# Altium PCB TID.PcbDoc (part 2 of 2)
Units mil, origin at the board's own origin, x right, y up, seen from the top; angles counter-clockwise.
Board outline 3536 x 3093.63 mil, 4 copper layers (Top Layer, Ground plane, Supply plane, Bottom Layer), stack 79.834 mil thick; 234 components, 122 nets, 591 pads, 178 vias.
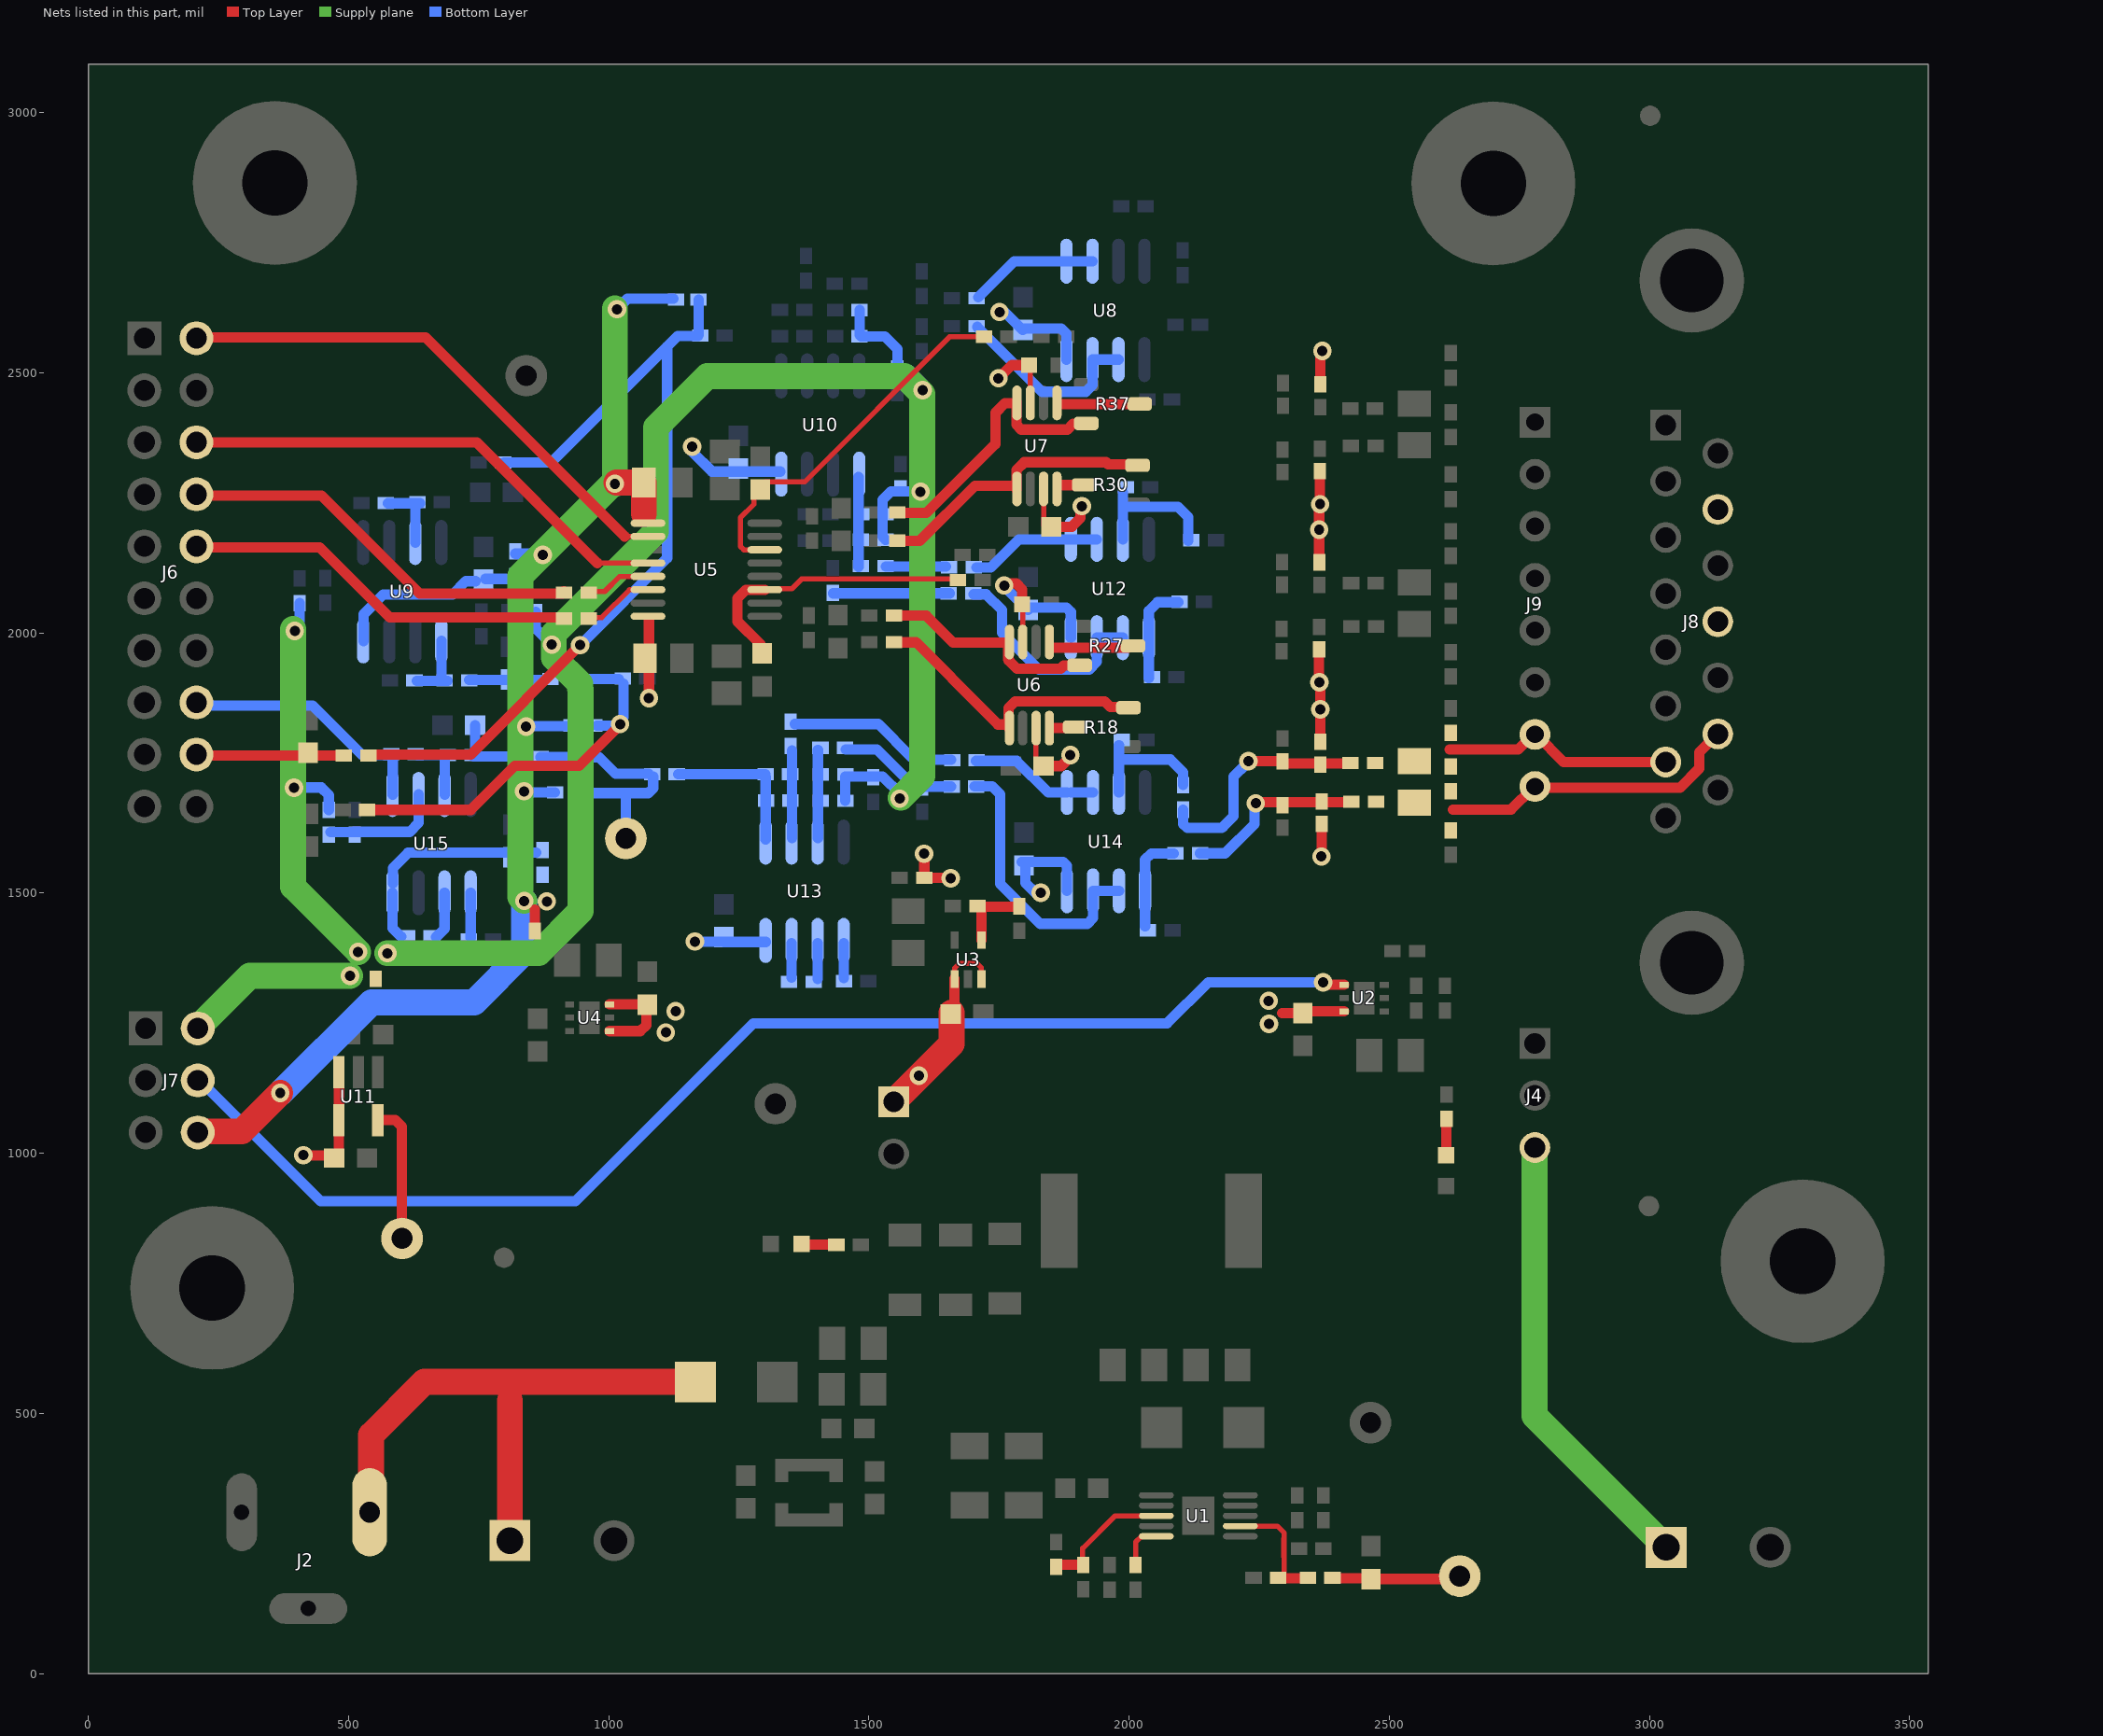
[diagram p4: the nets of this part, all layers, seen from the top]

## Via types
v1: diameter 35.43, hole 19.68, Top Layer to Bottom Layer, 169 vias
v2: diameter 19.68, hole 7.87, Top Layer to Bottom Layer, 9 vias

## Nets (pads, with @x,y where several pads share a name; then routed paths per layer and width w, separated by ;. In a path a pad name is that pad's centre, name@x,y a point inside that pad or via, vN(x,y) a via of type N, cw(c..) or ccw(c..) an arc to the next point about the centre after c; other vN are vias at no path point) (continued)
NetC65_1: C65.1 R60.2 U12.5 | length 192.8
  Bottom Layer w20: C65.1@2037.95,1913.26 U12.5@2037.95,1991.06 2037.95,2042.89 2054.17,2059.11 R60.2@2094.41,2059.11
NetC66_1: C66.1 R61.2 R62.1 | length 224.5
  Bottom Layer w20: R62.1@1430.96,2076.25 R61.2@1655.47,2076.25
NetC67_1: C67.1 R64.2 R65.1 | length 142.6
  Bottom Layer w20: R65.1@731.94,1909.76 R64.2@874.54,1909.76
NetC68_1: C68.1 R67.2 R68.1 | length 115.6
  Bottom Layer w20: R68.1@1532.78,2127.67 R67.2@1648.36,2127.67
NetC69_1: C69.1 R69.2 U12.3 | length 269.9
  Bottom Layer w20: U12.3@1987.95,2180.04 C69.1@1987.95,2270.07 ; 1987.98,2242.64 2094.03,2242.64 2113.8,2222.88 R69.2@2113.8,2177
NetC71_2: C71.2 R68.2 R70.1 U10.5 | length 172
  Bottom Layer w20: R68.2@1479.95,2127.42 U10.5@1479.95,2299.42
NetC72_1: C72.1 R74.2 R79.1 U13.1 | length 287.7
  Bottom Layer w20: R79.1@1133.08,1728.61 R74.2@1301.34,1728.61 ; U13.1@1301.52,1603.6 R74.2@1301.52,1723.05
NetC72_2: C72.2 R74.1 R78.2 U13.2 | length 168
  Bottom Layer w20: U13.2@1352,1606.16 R78.2@1352,1774.11
NetC76_1: C76.1 R75.2 U15.2 | length 232.4
  Bottom Layer w20: R75.2@465.03,1617.71 C76.1@511.27,1617.71 ; C76.1@510.32,1617.83 617.36,1617.83 634.9,1635.36 U15.2@634.9,1689.68
NetC77_1: C77.1 R76.2 U14.3 | length 247.9
  Bottom Layer w20: U14.3@1980.56,1693.57 C77.1@1980.56,1784.55 ; 1981.67,1756.87 2079.21,1756.87 2104.04,1732.04 R76.2@2104.04,1707.78
NetC78_1: C78.1 R77.2 R78.1 | length 322.5
  Bottom Layer w20: R78.1@1357.73,1825.16 1517.75,1825.16 1582.11,1760.81 C78.1@1602.64,1760.81 ; C78.1@1606.65,1756.33 R77.2@1657.57,1756.33
NetC79_1: C79.1 R80.2 R81.1 | length 137
  Bottom Layer w20: R81.1@740.18,1762.85 R80.2@821.54,1762.85 ; R81.1@743.46,1767.21 C79.1@743.46,1822.86
NetC80_1: C80.1 R85.2 R86.1 | length 231.4
  Bottom Layer w20: R86.1@1455.79,1776.37 1515.3,1776.37 1586.83,1704.84 R85.2@1657.56,1704.84
NetC81_1: C81.1 R87.2 U14.5 | length 188
  Bottom Layer w20: C81.1@2030.56,1436.07 U14.5@2030.56,1504.59 2030.56,1564.26 2042.51,1576.22 R87.2@2085.38,1576.22
NetC83_2: C83.2 R86.2 R88.1 U13.3 | length 168.8
  Bottom Layer w20: U13.3@1402,1606.16 R86.2@1402,1775
NetD1_2: D1.2 J1.1 J2.1 | length 1087.4
  Top Layer w50: J2.1@543.56,310.16 543.56,458.99 645.47,560.9 D1.2@1170.53,560.9 ; J1.1@810.05,255.8 810.05,525.22
NetD3_1: D3.1 R2.1 | length 57.4
  Top Layer w20: D3.1@1370.04,824.65 R2.1@1427.44,824.65
NetD4_1: D4.1 R12.1 | length 57.6
  Top Layer w20: D4.1@2609.49,996.1 R12.1@2609.49,1053.67
NetD17_2: D17.2 R41.1 R48.2 R49.1 | length 1659.7
  Top Layer w20: R41.1@548.56,1766.42 734.89,1766.42 v1@944.4,1975.93
  Bottom Layer w20: R49.1@798.89,2327.52 889.14,2327.52 1112.24,2550.62 ; v1@950.93,1982.47 1112.24,2143.78 1112.24,2550.62 ; R48.2@1172.05,2570.73 1132.35,2570.73 1112.24,2550.62 ; R48.2@1172.52,2572.56 D17.2@1172.52,2640.75
  other v1: 944.95,1976.82
NetD18_2: D18.2 R57.1 R63.2 R64.1 | length 758.6
  Top Layer w20: R57.1@535.95,1660.15 735.03,1660.15 819.57,1744.69 943.24,1744.69 v1@1020.53,1821.98
  Bottom Layer w20: R64.1@935.68,1911.44 R63.2@1019.61,1911.44 ; D18.2@977.25,1821.67 1012.59,1821.67 1028.75,1837.83 R63.2@1028.75,1902.67
  other v1: 1021.85,1824.97
NetD19_2: D19.2 R79.2 R80.1 TP6.1 | length 474.9
  Bottom Layer w20: R80.1@868.79,1761.49 980.97,1761.49 1012.87,1729.58 R79.2@1076.68,1729.58 ; D19.2@940.01,1693.87 941.51,1692.37 1075.99,1692.37 1085.48,1701.86 R79.2@1085.48,1724.31 ; TP6.1@1032.87,1605.27 1032.87,1686.57
NetJ4_3: J4.3 J5.1 | length 874.4
  Supply plane w50: J4.3@2779.1,1012.35 2779.1,495.67 J5.1@3032.01,242.76
NetR3_1: R3.1 R5.2 U1.3 | length 256.3
  Top Layer w10: R5.2@1910.87,213.86 1910.87,241.08 1973.22,303.43 U1.3@2063.99,303.43
  Top Layer w20: R3.1@1861.91,209.33 R5.2@1912.09,209.33
NetR6_2: R6.2 R7.2 TP2.1 | length 242.8
  Top Layer w20: R7.2@2398.32,183.43 R6.2@2467.3,183.43 ; R6.2@2464.7,181.94 TP2.1@2638.53,181.94
NetR7_1: R7.1 R10.2 U1.7 | length 216.2
  Top Layer w10: U1.7@2225.4,283.75 2284.71,283.75 2298.17,270.29 2298.17,260.07 2297.48,259.38 2297.48,225.09 2298.17,224.4 R10.2@2298.17,183.67
  Top Layer w20: R10.2@2298.17,183.67 R7.1@2348.81,183.67
NetR8_2: R8.2 U1.5 | length 99.7
  Top Layer w10: R8.2@2012.54,209.24 2012.54,252.89 2023.71,264.06 U1.5@2063.99,264.06
NetR15_1: R15.1 R16.2 U3.4 | length 141.5
  Top Layer w20: R15.1@1705.17,1474.08 R16.2@1789.27,1474.08 ; U3.4@1716.08,1409.64 R15.1@1716.08,1467.02
NetR18_2: R18.2 R21.1 U6.5 | length 553.7
  Top Layer w20: R21.1@1553.74,1982.15 1590.4,1982.15 1727.01,1845.54 1727.01,1845.08 1747.77,1824.32 U6.5@1767.18,1824.32 ; U6.5@1768.2,1818.26 1768.2,1856.16 1780.88,1868.84 1952.62,1868.84 ; 1952.79,1868.3 1963.56,1857.53 R18.2@1995.4,1857.53
NetR18_3: R18.3 U6.8 | length 42.5
  Top Layer w20: 1857.62,1817.65 R18.3@1900.14,1817.65
NetR22_1: R22.1 U5.13 | length 126.2
  Top Layer w10: R22.1@961.26,2079.79 992.05,2079.79 1021.06,2108.8 U5.13@1075.43,2108.8
NetR25_1: R25.1 R27.2 U6.4 | length 416.4
  Top Layer w20: R25.1@1550.75,2033.93 1609.99,2033.85 1661.99,1981.84 1767.95,1981.84 1767.95,1949.82 1768.84,1948.94 1768.84,1947.03 1784.5,1931.37 1865.1,1931.37 ; 1868.58,1931.81 1874.36,1937.59 R27.2@1905.9,1937.59
NetR26_1: R26.1 U5.14 | length 136.3
  Top Layer w10: R26.1@961.26,2029.79 986.63,2029.79 1040.05,2083.21 U5.14@1075.43,2083.21
NetR27_3: R27.3 U6.1 | length 142.2
  Top Layer w20: 1856.2,1972.01 R27.3@1998.43,1972.01
NetR30_2: R30.2 R33.1 U7.5 | length 531.9
  Top Layer w20: R33.1@1562.04,2177.07 1597.47,2177.07 1703.61,2283.21 U7.5@1781.09,2283.21 ; U7.5@1783.29,2276.78 1783.29,2313.04 1798.51,2328.25 1955.47,2328.25 1959.75,2323.98 2003.71,2323.98 R30.2@2006.61,2321.08
NetR30_3: R30.3 U7.8 | length 51.7
  Top Layer w20: U7.8@1865.87,2284.35 R30.3@1917.55,2284.35
NetR36_1: R36.1 R37.2 U7.4 | length 524
  Top Layer w20: R36.1@1559.13,2230.7 1610.46,2230.7 1743.04,2363.28 1743.04,2423.27 1761.31,2441.53 1773.86,2441.53 ; U7.4@1783.29,2442.91 1783.29,2400.44 1792.94,2390.78 ; 1793.9,2390.92 1881.17,2390.92 1892.43,2402.18 R37.2@1919.96,2402.18
NetR37_3: R37.3 U7.1 | length 144.9
  Top Layer w20: U7.1@1869.59,2439.58 R37.3@2014.45,2439.58
NetR46_1: R46.1 U8.1 U8.2 | length 246.5
  Bottom Layer w20: R46.1@1709.83,2645.53 1778.91,2714.6 U8.1@1879.56,2714.6 ; U8.1@1881.45,2714.6 U8.2@1929.56,2714.6
NetR50_2: R50.2 R51.1 U9.3 | length 136.9
  Bottom Layer w20: R51.1@575.95,2249.33 R50.2@637.45,2249.33 ; U9.3@628.74,2173.78 R50.2@628.74,2249.15
NetR52_1: R52.1 U8.6 U8.7 | length 376.4
  Bottom Layer w20: R52.1@1708.51,2588.21 1833.17,2463.55 1916.7,2463.55 1929.56,2476.41 U8.7@1929.56,2525.63 ; U8.7@1930.36,2525.63 U8.6@1979.56,2525.63
NetR61_1: R61.1 U12.6 U12.7 | length 424
  Bottom Layer w20: R61.1@1701.44,2074.34 1725.54,2074.34 1755.54,2044.34 1755.54,2000.74 1826.48,1929.8 1923.14,1929.8 1937.95,1944.61 U12.7@1937.95,1991.06 ; U12.7@1938.44,1991.06 U12.6@1987.95,1991.06
NetR65_2: R65.2 R66.1 U9.5 | length 132.1
  Bottom Layer w20: R66.1@631.04,1908.33 R65.2@690.25,1908.33 ; R65.2@678.74,1911.96 U9.5@678.74,1984.81
NetR67_1: R67.1 U12.1 U12.2 | length 249.1
  Bottom Layer w20: R67.1@1706.76,2125.78 1733.93,2125.78 1788.19,2180.04 U12.1@1887.95,2180.04 ; U12.1@1892.49,2180.04 U12.2@1937.95,2180.04
NetR71_1: R71.1 U13.7 | length 65.8
  Bottom Layer w20: R71.1@1351.52,1337.75 U13.7@1351.52,1403.6
NetR71_2: R71.2 U13.6 | length 68.4
  Bottom Layer w20: R71.2@1401.52,1335.17 U13.6@1401.52,1403.6
NetR72_2: R72.2 U13.5 | length 66.6
  Bottom Layer w20: R72.2@1451.52,1336.99 U13.5@1451.52,1403.6
NetR77_1: R77.1 U14.1 U14.2 | length 241.8
  Bottom Layer w20: R77.1@1705.88,1754.21 1783.91,1754.21 1844.56,1693.57 U14.1@1880.56,1693.57 ; U14.1@1888.55,1693.57 U14.2@1930.56,1693.57
NetR81_2: R81.2 R83.1 U15.3 | length 135.6
  Bottom Layer w20: R83.1@632.2,1765.69 R81.2@684.9,1765.69 ; U15.3@684.9,1689.68 R81.2@684.9,1765.69 ; R81.2@691.79,1765.69 R81.2@684.9,1765.69
NetR82_2: R82.2 U15.6 | length 92
  Bottom Layer w20: R82.2@668.32,1415.5 684.59,1431.76 U15.6@684.59,1500.74
NetR84_2: R84.2 U15.5 | length 86.3
  Bottom Layer w20: R84.2@734.59,1414.46 U15.5@734.59,1500.74
NetR85_1: R85.1 U14.6 U14.7 | length 545.2
  Bottom Layer w20: R85.1@1702.6,1705.49 1736.91,1705.44 1751.99,1690.36 1751.99,1518.33 1829.14,1441.18 1919.59,1441.18 1930.56,1452.14 U14.7@1930.56,1504.59 U14.6@1980.56,1504.59
NetTP5_1: TP5.1 U11.5 | length 259.3
  Top Layer w20: U11.5@557.26,1063.94 589.74,1063.94 602.19,1051.49 TP5.1@602.19,842.28
PWR_EN: J7.4 U2.4 | length 2453.3
  Top Layer w20: v1@2383.37,1323.96 U2.4@2413.27,1323.96
  Bottom Layer w20: J7.4@220.49,1137.18 220.49,1133.94 446.48,907.95 936,907.95 1277.51,1249.46 2072.79,1249.46 2152.03,1328.7 v1(2372.76,1328.7)
R: J6.16 R83.2 U15.1 | length 484.9
  Bottom Layer w20: J6.16@213.75,1860.75 430.95,1860.75 526.01,1765.69 R83.2@584.96,1765.69 ; U15.1@584.9,1689.68 R83.2@584.9,1763.99
R_M: C43.1 C44.2 J8.7 J9.7 R38.1 R39.2 | length 448
  Top Layer w20: 2615.99,1775.95 2747.65,1775.95 2775.3,1803.61 2783.29,1803.61 2834.77,1752.12 J8.7@3031.24,1752.12
R_M1: D13.1 D14.2 R38.2 R76.1 | length 431.9
  Top Layer w20: v1(2229.18,1753.78) D13.1@2288.35,1753.78 ; D13.1@2295.19,1749.08 R38.2@2423.5,1749.08
  Bottom Layer w20: R76.1@2104.04,1660.53 2104.04,1632.93 2111.6,1625.38 2178.2,1625.38 ; 2180.87,1627.91 2200.62,1647.66 2200.62,1723.89 v1@2225.6,1748.87
R_P: C44.1 C45.2 J8.14 J9.8 R39.1 R40.1 | length 591.3
  Top Layer w20: 2622.64,1660.27 2733.73,1660.27 2776.09,1702.62 3058.56,1702.62 3095.85,1739.91 3095.85,1770.67 J8.14@3131.24,1806.06 ; J9.8@2777.49,1704.45 J9.8@2780.5,1707.46
R_P1: D15.1 D16.2 R40.2 R87.1 | length 351.1
  Top Layer w20: v1@2249.82,1674.73 D15.1@2295.78,1674.73 ; D15.1@2293.22,1674.73 R40.2@2430.57,1674.83
  Bottom Layer w20: R87.1@2136.34,1576.66 2184.78,1576.66 2241.17,1633.06 v1@2241.17,1672.64
  other v1: 2243.25,1672.68
REFIO: C57.1 C58.1 C70.1 C71.1 C82.1 C83.1 J7.2 R44.1 R55.2 R56.2 R59.1 R70.2 R75.1 R88.2 | length 4573.5
  Supply plane w50: J7.2@211.57,1242.58 310.03,1341.04 v1(502.83,1341.04) ; v1@393.78,2007.48 393.78,1512.07 v1(518.54,1387.3) ; v1(574.41,1384.68) 865.23,1384.68 946.18,1465.64 946.18,1891.45 944.8,1892.83 944.8,1902.68 894.36,1953.13 894.36,1998.95 1090.73,2195.32 1090.73,2395.34 1189.38,2493.99 1568.49,2493.99 1602.7,2459.78 1602.7,1724.83 v1@1561.26,1683.39
  Bottom Layer w20: v1@399.32,1703.11 447.59,1703.11 462.14,1688.56 R75.1@462.14,1660.15 ; v1@406.03,2017.26 R44.1@406.03,2057.27 ; R59.1@859.58,2041 859.58,2008.75 v1(890.66,1977.67) ; C83.1@1454.62,1677.58 1454.62,1724.33 1526.34,1724.33 v1@1559.94,1690.73 ; R55.2@1482.05,2620.49 1482.05,2572.87 1484.69,2570.24 1530.43,2570.24 1554.74,2545.92 1554.74,2505.14 1578.12,2505.14 v1@1605.23,2478.04 ; R70.2@1532.09,2179.3 1526.46,2184.93 1526.46,2255.9 1542.7,2272.14 v1@1598.6,2272.14
  other v1: 1558.95,1681.74 395.37,1702.52 396.77,2004.07 1599.12,2271.63 1603.1,2466.88
REFIO_A: R24.1 R28.2 U5.3 | length 540.8
  Top Layer w10: U5.3@1301.12,2084.97 1351.69,2084.97 1370.76,2104.04 R24.1@1667.05,2104.04
  Top Layer w20: R28.2@1291.96,1977.8 1247.37,2022.39 1247.37,2067.1 1263.47,2083.21 U5.3@1299.84,2083.21
REFIO_B: R29.2 R35.1 U5.6 | length 720.7
  Top Layer w10: R29.2@1278.73,2274.22 1278.73,2247.24 1253.13,2221.64 1253.13,2166.68 1259.83,2159.98 U5.6@1299.84,2159.98 ; R29.2@1288.59,2276.57 1302.5,2290.48 1376.13,2290.48 1654.86,2569.21 R35.1@1720.43,2569.21
SCLK: J6.6 U5.12 | length 963.3
  Top Layer w10: 978.08,2134.39 U5.12@1075.43,2134.39
  Top Layer w20: J6.6@208.12,2366.1 746.38,2366.1 978.08,2134.39
SDI: J6.2 U5.10 | length 1015.7
  Top Layer w10: 1030.79,2185.57 U5.10@1075.43,2185.57
  Top Layer w20: J6.2@218.19,2568.15 648.21,2568.15 1030.79,2185.57
SDO_A: J6.8 R22.2 | length 782.7
  Top Layer w20: J6.8@210.89,2263.81 448.47,2263.81 636.5,2075.78 910.01,2075.78 R22.2@914.02,2079.79
SDO_B: J6.10 R26.2 | length 761.1
  Top Layer w20: J6.10@208.81,2164.8 444.23,2164.8 579.24,2029.79 R26.2@914.02,2029.79
SENSOR_GND: J8.10
SENSOR_UP: J8.12
SIN: C48.1 J6.18 R41.2 | length 282.2
  Top Layer w20: J6.18@208.95,1764.49 209.22,1764.77 R41.2@491,1764.77
V3_3_DC: C27.2 D17.1 D18.1 D19.1 J7.6 R17.2 R42.2 R73.2 U5.9 | length 2551.2
  Top Layer w20: R17.2@858.18,1427.34 858.22,1468.12
  Top Layer w50: J7.6@205.77,1042.06 294.92,1042.06 v1(368.79,1115.92) ; v1@1015.16,2289.06 C27.2@1067.54,2289.06 1067.54,2229.04
  Supply plane w50: v1(837.69,1485.15) 830.01,1492.83 830.01,2109.54 v1@1002.67,2282.2 ; v1(1011.86,2286.77) v1@1011.86,2624.08
  Bottom Layer w20: R42.2@820.09,2152.43 v1@871.31,2152.43 ; v1@839.27,1821 D18.1@930.02,1821 ; v1@842.89,1693.87 D19.1@896.7,1693.87 ; v1@870.58,2153.15 v1(873.47,2150.26) ; v1(1015.69,2622.27) 1036.04,2642.62 D17.1@1123.95,2642.62
  Bottom Layer w50: v1@369.48,1115.99 543.91,1290.43 741.42,1290.43 837.69,1386.7 v1(837.69,1485.15)
  other v1: 881.05,1484.11 837.59,1695.81 841.29,1819.99
V5_DC: C23.2 C24.2 C25.2 C33.2 C34.2 C47.2 C50.2 C59.2 C62.2 C73.2 C75.2 D6.1 D8.1 D10.1 D12.1 D14.1 D16.1 R14.2 U5.16 U6.3 U6.7 U7.3 U7.7 U8.8 U10.8 U11.3 U11.4 U12.8 U13.8 U14.8 | length 2372.9
  Top Layer w10: U6.3@1795.57,1982.71 C24.2@1795.57,2051.66 ; U7.3@1810.1,2442.25 C34.2@1810.1,2513.87 ; C23.2@1821.16,1753.28 U6.7@1821.16,1817.35 ; C33.2@1835.7,2207.96 U7.7@1835.7,2276.9
  Top Layer w20: v1@410.02,996.2 C59.2@474.86,996.2 ; C59.2@481.45,1004.34 U11.4@481.45,1064.41 ; U11.4@481.72,1064.06 U11.3@481.72,1158.55 ; U11.3@482.45,1158.43 U11.3@482.45,1163.54 ; v1(1077.21,1874.85) 1077.21,2024.5 ; v1@1606.53,1562.59 R14.2@1606.53,1529.56 v1@1643.89,1529.56 ; v1@1750.4,2490.87 1774.39,2514.85 C34.2@1807.74,2514.85 ; v1@1764.82,2095.26 1783.15,2095.26 1794.31,2084.11 C24.2@1794.31,2055.28 ; C23.2@1835.63,1744.36 1869.75,1744.36 v1@1885.85,1760.46 ; C33.2@1850.38,2204.18 1889.75,2204.18 1906.53,2220.97 v1@1906.53,2245.59 ; v1@2365.05,1909.18 D6.1@2365.05,1968.55 ; D8.1@2365.2,2136.99 v1(2365.2,2198.67) v1@2365.2,2244.62 ; v1@2366.48,2254.83 D12.1@2366.48,2311.29 ; D10.1@2367.3,2477.69 v1@2367.3,2538.17 ; D14.1@2367.53,1790.76 v1@2367.53,1850.29 ; v1(2367.62,1853.4) v1@2367.62,1898.15 ; v1@2369.92,1567.51 D16.1@2369.92,1633.27
  Bottom Layer w20: v1(1160.45,2358.14) 1160.45,2348.28 1198.38,2310.35 U10.8@1329.57,2310.35 ; v1@1167.96,1407.01 C75.2@1224.28,1407.01 ; C75.2@1221.84,1406.16 U13.8@1302,1406.16 ; v1@1761.43,2616.33 C47.2@1792.47,2585.29 ; v1@1766.75,2083.95 1769.51,2081.19 1769.51,2080.52 C62.2@1801.41,2048.63 ; C73.2@1793.67,1560.01 1873.48,1560.01 1880.56,1552.93 U14.8@1880.56,1504.59 ; C47.2@1796.17,2582.26 1795.5,2582.26 C47.2@1792.47,2585.29 ; C73.2@1800.94,1554.33 1800.94,1519.92 1819.93,1500.93 v1(1830.36,1500.93) ; C62.2@1806.08,2044.62 1805.41,2044.62 C62.2@1801.41,2048.63 ; U8.8@1879.56,2525.63 1879.56,2575.19 1869.46,2585.29 C47.2@1792.47,2585.29 ; U12.8@1887.95,1991.06 1887.95,2040.36 1879.69,2048.63 C62.2@1801.41,2048.63
  other v1: 413.01,996.46 1165.57,1407.01 1657.18,1528.68 2369.63,1570.44 1605.85,1575.8 1887.1,1765.47 2365.8,1905.4 1760,2091.4 1908.97,2243.76 2367.01,2247.64 1748.85,2489.46 2371.42,2542.07 1750.97,2616.83
V6_DC: C17.1 C19.1 C21.1 J3.1 U2.6 U3.1 U3.3 U4.4 U4.6 | length 647.2
  Top Layer w10: U3.1@1664.9,1334.83 1664.9,1356.13 1673.93,1365.16 1707.59,1365.16 1715.7,1357.05 U3.3@1715.7,1339.68
  Top Layer w20: U4.4@1001.72,1235.05 1060.99,1235.05 1072.16,1246.22 C21.1@1072.16,1277.13 ; U4.6@1001.72,1286.23 C21.1@1068.16,1286.23 ; C19.1@1664.08,1276.32 U3.1@1664.08,1335.56 ; 2294.46,1269.71 C17.1@2333.77,1269.71 ; 2354.56,1272.78 U2.6@2413.27,1272.78
  Top Layer w50: J3.1@1545.27,1096.56 1659.04,1210.33 C19.1@1659.04,1270.42
  other v1: 1595.75,1149.24 1109.66,1232.42 2268.76,1248.86 1128.5,1273.24 2268.17,1293.06
V_DC1: C49.2 R42.1 U9.8 | length 343.2
  Bottom Layer w20: U9.8@528.74,1984.81 528.74,2035.87 566.9,2074.03 700.12,2074.03 725.65,2099.56 C49.2@744.25,2099.56 ; C49.2@762.97,2103.95 R42.1@813.19,2103.95
V_DC2: C74.2 R73.1 R82.1 U15.8 | length 407.9
  Bottom Layer w20: U15.8@584.59,1500.74 584.59,1432.94 R82.1@601.01,1416.51 ; U15.8@585.36,1519.31 585.36,1548.7 614.63,1577.97 860.69,1577.97
pads on no net: FID1.1 FID2.1 FID3.1 H1.1 H2.1 H3.1 H4.1 J8.5 J8.6 J8.8 J8.13 J8.15 J8.16 J8.17 U1.6 U2.5 U4.5 U15.7

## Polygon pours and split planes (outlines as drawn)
A_P on Top Layer "Top Layer-A_P" (solid, remove dead copper, pour order 40): 2629.77,2503.09 2626.42,2506.44 2618.67,2506.44 2519.79,2506.44 2456.53,2443.18 2456.53,2419.7 2468.09,2408.13 2625.15,2408.13 2629.87,2412.86
A_M on Top Layer "Top Layer-A_M" (solid, remove dead copper, pour order 37): 2629.91,2389.97 2627.52,2392.36 2624.84,2392.36 2478.51,2392.36 2457.65,2371.51 2457.65,2347.67 2516.56,2288.76 2625.21,2288.76 2629.79,2293.34
B_P on Top Layer "Top Layer-B_P" (solid, remove dead copper, pour order 36): 2629.79,2046.43 2627.38,2048.84 2623.56,2048.84 2482.89,2048.84 2458.54,2024.5 2458.54,2000.64 2511.35,1947.83 2624.67,1947.83 2629.82,1952.98
B_M on Top Layer "Top Layer-B_M" (solid, remove dead copper, pour order 35): 2629.9,2161.26 2627.1,2164.06 2622.9,2164.06 2514.37,2164.06 2458.09,2107.78 2458.09,2083.89 2477.47,2064.51 2628.18,2064.49 2629.97,2066.38
R_P on Top Layer "Top Layer-R_P" (solid, remove dead copper, pour order 34): 2629.78,1612.93 2629.78,1709.24 2627.28,1711.74 2482.46,1711.74 2458.3,1687.58 2458.3,1663.9 2516.83,1605.34 2614.81,1605.34 2625.9,1605.34 2629.79,1609.23
R_M on Top Layer "Top Layer-R_M" (solid, remove dead copper, pour order 33): 2620.97,1823.57 2518.2,1823.57 2456.73,1762.09 2456.73,1738.12 2467.2,1727.65 2628.34,1727.65 2629.98,1729.28 2629.9,1820.98 2627.26,1823.62 2625.96,1823.62
REFIO on Top Layer "Top Layer-refio" (solid, remove dead copper, pour order 38): 508.58,1404.58 581.25,1404.58 593.1,1392.74 593.1,1335.95 577.38,1320.22 496.75,1320.22 483.04,1333.94 483.04,1379.04
NetC1_1 on Top Layer "Top Layer-SW" (solid, remove dead copper, pour order 49): 2204.94,336.63 2195.56,336.63 2184.03,348.15 2164.19,367.99 2164.19,402.31 2164.19,940.36 2184.83,961 2256.09,961 2259.64,957.46 2259.64,342.4 2253.75,336.51
GND on Top Layer "Top Layer-PS_GND" (solid, remove dead copper, pour order 58): 1975.42,1141.42 1287.8,1141.42 1247.49,1101.11 1244.13,1097.75 1244.13,992.48 1244.13,920.8 1054.87,731.54 1041.44,718.11 591.24,718.11 395.25,522.12 252.34,379.22 252.34,164.66 252.34,122.03 294.98,79.4 314.65,59.72 490.09,59.72 2644.57,59.72 2738.03,153.18 2738.03,320.79 2525.37,533.45 2525.37,818.38 2201.87,1141.88
GND on Top Layer "Top Layer-ENC_GND" (solid, remove dead copper, pour order 56): 2684.34,1454.54 2340.04,1454.54 2323.38,1437.88 2211.18,1325.68 2211.18,1207.48 2363.95,1054.71 2590.83,827.83 2590.83,555.81 3029.49,117.15 3277.6,117.15 3330.36,169.9 3330.36,464.22 2932.58,862 2932.58,1206.29 2775.96,1362.91
V3_3_DC on Top Layer "Top Layer-V3_3_out" (solid, remove dead copper, pour order 45): 880.08,1501.47 886.74,1501.47 898.06,1490.15 898.06,1479.33 885.41,1466.68 877.59,1466.68 876.26,1465.35 867.43,1456.52 849.62,1456.52 838.8,1467.34 835.31,1467.34 832.31,1467.34 820.82,1478.83 820.82,1491.98 830.48,1501.63
V6_DC on Top Layer "Top Layer-ldoenc-vin" (solid, remove dead copper, pour order 44): 2252.78,1247.63 2252.78,1300.4 2261.24,1308.86 2276.35,1308.86 2285.41,1299.8 2285.41,1291.74 2299.71,1277.44 2299.71,1260.32 2287.42,1248.03 2287.42,1245.21 2276.55,1234.34 2266.07,1234.34 2252.78,1247.63
NetD1_2 on Top Layer "Top Layer-vin" (solid, remove dead copper, pour order 46): 900.45,552.7 829.74,481.98 819.21,481.98 788.36,481.98 721.41,548.94
NetC5_1 on Top Layer "Top Layer-filter" (solid, remove dead copper, pour order 48): 1287.25,597.1 1287.25,499.2 1321.67,464.78 1321.67,382.93 1335.44,369.17 1442.52,369.17 1452.46,379.11 1452.46,655.23 1440.99,666.7 1352.27,666.7 1285.72,600.16
NetC2_1 on Top Layer "Top Layer-Vdcdc" (solid, remove dead copper, pour order 41): 1902.49,851.76 1902.49,793.71 1888.12,779.35 1531.83,779.35 1521.48,789.69 1521.48,1013.81 1532.98,1025.31 1849.62,1025.31 1902.49,972.44
NetC15_2 on Top Layer "Top Layer-Venc_fb" (solid, remove dead copper, pour order 43): 2537.86,1396.1 2537.86,1307.54 2539.21,1306.19 2624.03,1306.19 2626.27,1308.43 2626.27,1347.62 2573.25,1400.64 2542.4,1400.64
NetC18_1 on Top Layer "Top Layer-ldo5v" (solid, remove dead copper, pour order 42): 1570.95,1440.52 1607.41,1440.52 1655.02,1392.91 1674.49,1392.91 1676.99,1395.41 1676.99,1488.63 1675.33,1490.3 1544.32,1490.3 1543.32,1489.3 1543.32,1442.19 1544.98,1440.52
NetC15_1 on Top Layer "Top Layer-ldo5V" (solid, remove dead copper, pour order 47): 2544.22,1290.02 2775.83,1290.02 2808.91,1256.93 2808.91,1179.08 2787.18,1157.34 2523.78,1157.34 2517.62,1163.51 2517.62,1267.31 2540.32,1290.02
V6_DC on Top Layer "Top Layer-ldo_3_3V-vin" (solid, remove dead copper, pour order 39): 1055.58,1305.53 1119.83,1305.53 1145.06,1280.3 1145.06,1242.96 1116.13,1214.03 1108.06,1214.03 1055.58,1266.5
GND on Top Layer "Top Layer-GND" (solid, remove dead copper, pour order 57): 139.82,2672.04 946.87,2672.04 1162.42,2887.59 2102.31,2887.59 2383.59,2606.31 2706.86,2606.31 2850.17,2463 2850.17,1623.33 2850.17,1563.7 2791.9,1505.43 2759.38,1472.91 2434.16,1472.91 2252.58,1472.91 2161.79,1382.12 2034.49,1254.82 1296.67,1254.82 960.53,918.69 156.28,918.69 62.78,1012.19 62.78,2594.99
V3_3_DC on Bottom Layer "Bottom Layer-3_3V" (solid, remove dead copper, pour order 55): 868.04,1550.99 860,1550.99 826.12,1517.12 819.79,1510.78 819.79,1475.44 829.54,1465.69 887.3,1465.69 888.76,1465.69 898.51,1475.44 898.51,1536.86 884.37,1550.99
GND on Bottom Layer "Bottom Layer-GND" (solid, remove dead copper, pour order 62): 141.05,2672.44 947,2672.44 1163.72,2889.16 2101.36,2889.16 2384.3,2606.23 2707.03,2606.23 2850.17,2463.09 2850.17,1623.33 2850.17,1563.7 2791.9,1505.43 2759.38,1472.91 2434.16,1472.91 2252.58,1472.91 2161.79,1382.12 2033.91,1254.24 1300.07,1254.24 964.52,918.69 332.44,918.69 156.28,918.69 62.78,1012.19 62.78,2594.16
NetD19_2 on Bottom Layer "Bottom Layer-testpt" (solid, pour order 54): 1041.45,1665.89 1062.18,1686.62 1062.18,1694.78 1015.83,1694.78 1007.18,1686.13 1031,1662.3 1033.45,1662.3
V3_3_DC on Supply plane "Supply plane-V3_3" (solid, remove dead copper, pour order 32): 846.08,1459.64 883.46,1459.64 899.48,1475.67 899.48,1566.99 855.42,1611.05 855.42,2090.36 926.19,2161.12 1036.74,2271.67 1036.74,2613.2 1036.74,2636.7 1019.38,2654.06 807.85,2654.06 733.73,2579.94 733.73,1551.17 825.26,1459.65
REFIO on Supply plane "Supply plane-REFIO" (solid, remove dead copper, pour order 51): 620.33,1405.15 600.94,1424.53 502.59,1424.53 495.64,1424.53 473.67,1402.56 473.67,1379.19 456.42,1361.95 456.42,1354.44 456.42,1316.89 456.98,1316.34 531.52,1316.34
V5_DC on Supply plane "Supply plane-V5_DC" (solid, remove dead copper, pour order 61): 1176.04,1329.92 2108.84,1329.92 2251.66,1472.74 2452.37,1472.74 2507.48,1527.86 2507.48,2482.71 2327.28,2662.91 1341.5,2662.91 1135.83,2457.24 1135.83,2027.34 1044.6,1936.1 1044.6,1830.95 1097.17,1778.37 1097.17,1535.59 853.58,1291.99 470.07,1291.99 354.91,1176.82 354.91,944.87 381.48,918.29 725.79,918.29 1136.5,1329
V6_DC on Supply plane "Supply plane-V6DC" (solid, remove dead copper, pour order 53): 2266.63,1302.24 2278.87,1302.24 2295.69,1285.42 2295.69,1254.82 2287.28,1246.41 2277.48,1236.6 1788.55,1236.6 1728.08,1236.6 1561.22,1069.74 1522.02,1069.74 1382.03,1209.73 1099.82,1209.73 1091.43,1218.12 1091.43,1260.27 1132.72,1301.56 2274.58,1301.56 2275.7,1302.68
GND on Ground plane "Ground plane-PS_GND" (solid, remove dead copper, pour order 60): 1972.22,1141.42 1284.61,1141.42 1244.29,1101.11 1240.93,1097.75 1240.93,992.48 1240.93,920.8 1051.67,731.54 1038.24,718.11 588.04,718.11 392.06,522.12 249.15,379.22 249.15,164.66 249.15,122.03 291.78,79.4 311.46,59.72 486.9,59.72 2641.37,59.72 2734.83,153.18 2734.83,324.54 2525.59,533.78 2525.59,814.96 2198.67,1141.88
GND on Ground plane "Ground plane-GND" (solid, remove dead copper, pour order 59): 139.87,2672.44 946.97,2672.44 1163.7,2889.16 2098.98,2889.16 2381.54,2606.6 2706.36,2606.6 2850.17,2462.8 2850.17,1623.33 2850.17,1563.7 2791.9,1505.43 2759.38,1472.91 2434.16,1472.91 2252.58,1472.91 2161.79,1382.12 2034.49,1254.82 1299.99,1254.82 963.86,918.69 332.44,918.69 156.28,918.69 62.78,1012.19 62.78,2595.35
GND on Ground plane "Ground plane-GND connection" (solid, remove dead copper, pour order 50): 1241.01,1093.34 1199.3,1135.04 1168.57,1135.04 1168.57,1190.65 1284.9,1306.98 2036.3,1306.98 2233.12,1503.79 2314.33,1503.79 2326.5,1491.62 2301.17,1466.29 2301.17,1458.59 2305.22,1454.54 2348.02,1454.54 2362.62,1439.94 2362.62,1274.79 2258.72,1170.89 2226.53,1170.89 2216.29,1160.65 2205.31,1149.67 2205.31,1110.17 2159.22,1064.07 1271.74,1064.07 1269.54,1064.07 1241.74,1091.87
GND on Ground plane "Ground plane-ENC_GND" (solid, remove dead copper, pour order 52): 2684.47,1454.31 2340.17,1454.31 2323.51,1437.65 2210.57,1324.72 2210.57,1207.99 2364.08,1054.48 2591.9,826.66 2591.9,555.4 3030.38,116.92 3277.73,116.92 3330.49,169.68 3330.49,463.99 2933.44,861.04 2933.44,1205.34 2776.09,1362.68

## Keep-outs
Keep-Out Layer:
  lines w6: -3,0 ccw(c0,0) 0,-3 ; -3,0 ccw(c0,0) 0,-3 ; -3,0 -3,3093.63 ; -3,3093.63 cw(c0,3093.63) 0,3096.63 ; -3,3093.63 cw(c0,3093.63) 0,3096.63 ; 0,-3 3536,-3 ; 0,3096.63 3536,3096.63 ; 3536,-3 ccw(c3536,0) 3539,0 ; 3536,-3 ccw(c3536,0) 3539,0 ; 3536,3096.63 cw(c3536,3093.63) 3539,3093.63 ; 3536,3096.63 cw(c3536,3093.63) 3539,3093.63 ; 3539,0 3539,3093.63
  text ".Layer_Name" at 577,-858.49 h60

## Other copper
Top Layer:
  pour cut-out: 2163.87,520.61 2163.87,553.51 2155.65,561.74 2103.89,561.74 2103.89,429.98 2097.19,423.28 2023.36,423.28 2016.52,423.27 2015.68,422.43 2015.68,418.02 2016.59,417.11 2160.79,417.11 2165.24,421.56
  pour cut-out: 1180.84,1899.01 1184.87,1903.04 1184.87,2326.34 1179.94,2331.27 1177.25,2331.27 1173.22,2327.24 1173.22,1902.14 1176.36,1899.01
  pour cut-out: 1835.67,761.61 1835.67,746.44 1922.9,659.2 2152.37,659.2 2158.06,664.89 2158.06,944.3 2181.45,967.68 2255.41,967.68 2255.41,987.28 2161.85,1080.84 1922.9,1080.84 1859.69,1017.62 1907.73,969.58 1907.73,777.41 1901.41,771.09 1845.78,771.09 1835.67,760.98
  pour cut-out: 2037.31,195.59 2037.31,143.87 2043.55,137.64 2204.63,137.64 2214.6,147.61 2214.6,243.89 2213.04,245.45 2210.55,245.45 2210.55,150.11 2202.44,142.01 2202.44,140.76 2045.1,140.76 2041.05,144.81 2041.05,196.22 2037.94,199.33
  pour cut-out: 1919.31,689.1 1907.75,677.54 1907.75,640.2 1911.31,636.65 2150.43,636.65 2161.99,648.2 2161.99,663.32 2136.21,689.1
  pour cut-out: 2767.52,2248.34 2762.43,2248.34 2739.38,2225.3 2739.38,2185.64 2762.87,2162.15 2800.98,2162.15 2821.58,2182.76 2821.58,2225.08 2798.54,2248.12
  pour cut-out: 1592.07,1061.29 1592.07,1046.72 1571.18,1025.82 1503.07,1025.82 1503.07,1058.35 1506.01,1061.29
  text ".Layer_Name" at 577,-858.49 h60
Ground plane:
  pour cut-out: 2767.52,2248.34 2762.43,2248.34 2739.38,2225.3 2739.38,2185.64 2762.87,2162.15 2800.98,2162.15 2821.58,2182.76 2821.58,2225.08 2798.54,2248.12
  pour cut-out: 2813.84,2225.98 2853.7,2225.98 2858.58,2221.09 2858.58,2187.63 2853.61,2182.66 2814.81,2182.66 2810.06,2187.41 2810.06,2222.2
Bottom Layer:
  pour cut-out: 2767.52,2248.34 2762.43,2248.34 2739.38,2225.3 2739.38,2185.64 2762.87,2162.15 2800.98,2162.15 2821.58,2182.76 2821.58,2225.08 2798.54,2248.12
  text ".Layer_Name" at 577,-858.49 h60

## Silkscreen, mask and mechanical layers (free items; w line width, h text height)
Top Overlay:
  lines w10: 85.92,1568.73 100.92,1583.73 ; 86.77,1342.78 101.77,1327.78 ; 100.92,1540.41 100.92,1583.73 ; 101.77,1371.1 101.77,1327.78 ; 115.92,1568.73 100.92,1583.73 ; 116.77,1342.78 101.77,1327.78
  text ".CopyrightYear" at 3220.15,2911.04 h60
  text "©" at 3140.37,2906.35 h105
  text ".PRJ_Number" at 1442.33,2806.88 h60
  text ".PCB_Rev" at 2114.75,2806.88 h60
  text "SDI" at 279.42,2551.37 h30
  text "CSN" at 279.42,2452.76 h30
  text "SCLK" at 279.42,2348.62 h30
  text "SDO_A" at 279.42,2257.39 h30
  text "SDO_B" at 279.42,2156.93 h30
  text "A" at 279.42,2062.1 h30
  text "B" at 279.42,1955.95 h30
  text "R" at 279.42,1844.38 h30
  text "SIN" at 279.42,1758.06 h30
  text "COS" at 279.42,1641.6 h30
  text "GND" at 87.65,1500.92 h30 r270
  text "REFIO" at 275.52,1222.86 h30
  text "PWR_EN" at 275.52,1121.58 h30
  text "3.3V" at 275.52,1023.22 h30
  text "24V" at 731.73,50.41 h40
  text "GND" at 988.82,48.46 h40
  text "Ext Venc" at 2862.51,41.19 h40
  text "GND" at 3216.93,37.75 h40
  text ".Layer_Name" at 577,-858.49 h60
Bottom Overlay:
  lines w8: 843.42,1949.37 1009.9,1950.08 1031.54,1972.97 1031.67,1972.97 ; 1271.99,2739.63 1282.7,2739.61 ; 1282.54,2596.2 1295.84,2596.2 ; 1282.55,2737.98 1282.66,2596.65 ; 1620.88,2212.28 1641.18,2233.76 ; 1629.89,2503.61 1687.23,2443.7
  lines w10: 1573.03,1610.06 1582.47,1621.52
  text ".Layer_Name" at 577,-858.49 h60
Top Paste:
  text ".Layer_Name" at 577,-858.49 h60
Bottom Paste:
  text ".Layer_Name" at 577,-858.49 h60
Top Solder:
  text ".Layer_Name" at 577,-858.49 h60
  text ".Layer_Name" at 577,-858.49 h60
Bottom Solder:
  text ".Layer_Name" at 577,-858.49 h60
Drill Guide:
  text ".Layer_Name" at 577,-858.49 h60
M1 Board Outline:
  the board outline again, w10
  text ".Layer_Name" at 577,-858.49 h60
M2 Board Dimensions:
  rectangle: 125,-400 500,-275
  rectangle: 0,-275 125,-150
  lines w7: 0,-275 1000,-275 ; 125,-400 125,-150 ; 250,-400 250,-150 ; 500,-400 500,-150 ; 750,-400 750,-150 ; 0,-400 0,-150 1000,-150 1000,-400 0,-400
  text ".Layer_Name" at 577,-858.49 h60
M3 3D STEP Top:
  text ".Layer_Name" at 577,-858.49 h60
M4 3D STEP Bottom:
  text ".Layer_Name" at 577,-858.49 h60
M5 Assembly Top:
  lines w10: -292,-930.17 6308,-930.17 ; -292,-726.83 6310,-726.83 ; -292,-523.5 -292,-1133.5 3713,-1133.5 6310,-1133.5 6310,-523.5 -291.5,-523.5 -291.5,-1133.5 1284,-1133.5 ; 2173,-1133.5 2173,-523.5 ; 3440,-726.83 3440,-523.5 ; 4280,-726.83 4280,-523.5 ; 4902,-1140 4902,-937.17
  text "COMPONENTS MARKED 'DNP' SHOULD NOT BE POPULATED." at 1153.5,-318.5 h60
  text "ASSEMBLY VARIANT:" at 1153,-434 h60
  text ".VariantName" at 2189,-434 h60
  text "PCB VIEWED FROM TOP SIDE" at -228.5,-655.67 h60
  text "BOARD #:" at 2248,-655.67 h60
  text ".PRJ_Number" at 2793.5,-655.67 h60
  text "REV:" at 3638,-655.67 h60
  text ".PCB_Rev" at 3929.5,-655.67 h60
  text "SVN REV:" at 4476,-655.67 h60
  text ".VersionControl_RevNumber" at 4982,-655.67 h60
  text "PLOT NAME =" at -228.5,-1064.34 h60
  text ".plot_File_Name" at 577,-1064.34 h60
  text "GENERATED    :" at 2250,-1064.34 h60
  text ".Print_Date" at 3119.5,-1064.34 h60
  text ".Print_Time" at 3848.5,-1064.34 h60
  text "TEXAS INSTRUMENTS" at 5113,-1064.34 h60
M6 Assembly Bottom:
  lines w10: -292.5,-727.33 6309.5,-727.33 ; -290.5,-930.67 6309.5,-930.67 ; 1115.5,-1140.5 1115.5,-937.67 ; 1737.5,-727.33 1737.5,-524 ; 2577.5,-727.33 2577.5,-524 ; 3844.5,-1134 3844.5,-524 ; 4733.5,-1134 6309,-1134 6309,-524 -292.5,-524 -292.5,-1134 2304.5,-1134 6309.5,-1134 6309.5,-524
  text "COMPONENTS MARKED 'DNP' SHOULD NOT BE POPULATED." at 6102,-318 h60
  text ".VariantName" at 5058,-434 h60
  text "ASSEMBLY VARIANT:" at 6097,-434 h60
  text ".VersionControl_RevNumber" at 1035.5,-656.17 h60
  text "SVN REV:" at 1541.5,-656.17 h60
  text ".PCB_Rev" at 2088,-656.17 h60
  text "REV:" at 2379.5,-656.17 h60
  text ".PRJ_Number" at 3224,-656.17 h60
  text "BOARD #:" at 3769.5,-656.17 h60
  text "PCB VIEWED FROM BOTTOM SIDE" at 6246,-656.17 h60
  text "TEXAS INSTRUMENTS" at 904.5,-1064.84 h60
  text ".Print_Time" at 2169,-1064.84 h60
  text ".Print_Date" at 2898,-1064.84 h60
  text "GENERATED    :" at 3767.5,-1064.84 h60
  text ".plot_File_Name" at 5440.5,-1064.84 h60
  text "PLOT NAME =" at 6246,-1064.84 h60
M9 Title Sheet:
  drawing of 57 lines, arcs and shapes, not listed
  text "1" at 739.84,8036.5 h70
  text "2" at 3235.5,8036.5 h70
  text "3" at 5724.84,8036.5 h70
  text "4" at 8231.51,8036.5 h70
  text "5" at 10730.5,8036.5 h70
  text "6" at 13235.5,8036.5 h70
  text "A" at -416.5,6893.5 h70
  text "A" at 14383.5,6893.5 h70
  text "B" at -416.5,4513.5 h70
  text "B" at 14383.5,4513.5 h70
  text "C" at -416.5,2138.5 h70
  text "C" at 14383.5,2138.5 h70
  text "PROJECT TITLE:" at 11343.5,277.5 h45
  text ".PRJ_Title" at 11393.5,144.17 h70
  text "DESIGNED FOR:" at 11343.5,-23.5 h45
  text ".PRJ_Customer" at 11393.5,-163.5 h70
  text "D" at -416.5,-231.5 h70
  text "D" at 14383.5,-231.5 h70
  text "FILE NAME:" at 11343.5,-323.5 h45
  text ".PCB_File_Name_No_Path" at 11393.5,-443.5 h70
  text "Texas Instruments (TI) and/or its licensors do not warrant the accuracy or completeness of this specification" at 6374,-605.34 h45
  text "ENGINEER:" at 11343.5,-613.5 h45
  text "LAYOUT BY:" at 12848.5,-613.5 h45
  text "or any information contained therein. TI and/or its licensors do not warrant that this design will meet" at 6329.01,-718 h45
  text ".PRJ_Engineer" at 11393.5,-768.49 h70
  text ".PCB_Layout" at 12899,-768.49 h70
  text "the specifications, will be suitable for your application or fit for any particular purpose, or will operate in" at 6329.01,-830.67 h45
  text ".Layer_Name" at 577,-858.49 h60
  text "ALTIUM DESIGNER VERSION:" at 12848.5,-923.5 h45
  text "an implementation. TI and/or its licensors do not warrant that the design is production worthy. You should" at 6329.01,-943.33 h45
  text "completely validate and test your design implementation to confirm the system functionality for your application." at 6374,-1056 h45
  text ".print_Scale" at 11393.5,-1056.83 h70
  text ".Application_BuildNumber" at 12899,-1056.83 h70
  text "1" at 739.84,-1263.5 h70
  text "2" at 3235.5,-1263.5 h70
  text "3" at 5724.84,-1263.5 h70
  text "4" at 8231.51,-1263.5 h70
  text "5" at 10730.5,-1263.5 h70
  text "6" at 13235.5,-1263.5 h70
M10 Fab Notes:
  drawing of 185 lines, arcs and shapes, not listed
  text "DESIGN INFORMATION" at 12381.02,5910 h60
  text "MIN. TRACK WIDTH:" at 11736.46,5730 h60
  text "8" at 12832.7,5730 h60
  text "MIL" at 12987.46,5730 h60
  text "MIN. CLEARANCE:" at 11736.46,5598 h60
  text "0.2" at 12772.7,5598 h60
  text "mm" at 12987.46,5598 h60
  text "MIN. VIA PAD SIZE:" at 11736.46,5466 h60
  text "24" at 12802.71,5466 h60
  text "MIL" at 12987.46,5466 h60
  text "0.05mm (2MIL)" at 12431.46,5324.29 h60
  text "MINIMUM ANNULAR RING" at 11407.23,5320 h60
  text "EXTERNAL" at 13139.46,5320 h60
  text "PER" at 11607.23,5202 h60
  text "IPC-D-275 CLASS 2 LEVEL C" at 11827.23,5202 h60
  text "MIL, HOLES" at 13315.46,5089.71 h60
  text "+/-" at 12923,5089 h60
  text "+/-" at 13777,5089 h60
  text "REGISTRATION TOLERANCES:" at 11407.23,5084 h60
  text "METAL" at 12607,5084 h60
  text "5" at 13183.2,5084 h60
  text "3" at 14016.2,5084 h60
  text "MIL" at 14132.46,5084 h60
  text "MATERIAL:" at 11332.46,4874.54 h60
  text "FR-4 High Tg" at 12318.9,4734.21 h60
  text "FR-408" at 11753.46,4725.64 h60
  text "X" at 12165.46,4725.64 h60
  text "OTHER" at 13241.46,4725.64 h60
  text "62 MIL (1.6mm) +/-10%" at 12073.56,4562.92 h60
  text "THICKNESS:" at 11407.23,4558.64 h60
  text "X" at 11945.4,4558.64 h60
  text "OTHER" at 13358.46,4558.64 h60
  text "TOLERANCE:" at 11407.23,4400.64 h60
  text "X" at 12246.53,4400.64 h60
  text "ANSI IPC-6012 TYPE 3 CLASS 2" at 12433.48,4400.64 h60
  text "OTHER +/-" at 12433.46,4244.64 h60
  text "BOW & TWIST:" at 11407.23,4087.64 h60
  text "X" at 12246.53,4087.64 h60
  text "ANSI IPC-6012 TYPE 3 CLASS 2" at 12433.48,4087.64 h60
  text "OTHER +/-" at 12433.46,3929.13 h60
  text "DRILLING:" at 11332.46,3790.64 h60
  text "REFERENCE:" at 11407.23,3673.64 h60
  text "X" at 12055.46,3673.64 h60
  text "AS SHOWN" at 12242.46,3673.64 h60
  text "X" at 12956.46,3673.64 h60
  text "NC_DRILL FILES" at 13093.46,3673.64 h60
  text "PTH MIN COPPER THICKNESS:" at 11407.23,3515.64 h60
  text "X" at 12757.46,3515.64 h60
  text "1MIL" at 12894.46,3515.64 h60
  text "OTHER" at 13391.46,3515.64 h60
  text "BOARD FINISH:" at 11332.46,3356.64 h60
  text "SILKSCREEN:" at 11487.68,3238.64 h60
  text "X" at 12436.46,3238.64 h60
  text "TOP" at 12562.46,3238.64 h60
  text "X" at 12946.46,3238.64 h60
  text "BOTTOM" at 13073.46,3238.64 h60
  text "SILKSCREEN COLOR:" at 11487.68,3071.64 h60
  text "X" at 12435.42,3071.64 h60
  text "WHITE" at 12562.46,3071.64 h60
  text "OTHER" at 13073.46,3071.64 h60
  text "SOLDER RESIST COLOR:" at 11487.68,2901.64 h60
  text "X" at 12055.42,2742.44 h60
  text "GREEN" at 12182.46,2742.44 h60
  text "BLUE" at 12773.46,2742.44 h60
  text "OTHER" at 13311.46,2742.44 h60
  text "IMMERSION GOLD (ENIG)" at 12393.46,2553.92 h60
  text "ENEPIG" at 13731,2550.64 h60
  text "SURFACE FINISH:" at 11332.46,2549.64 h60
  text "X" at 12206.51,2549.64 h60
  text "IMM. TIN/SILVER OR EQUIV" at 11662,2392.64 h60
  text "OTHER" at 13093.46,2392.64 h60
  text "ARRAY/PANEL:" at 11332.46,2213.64 h60
  text "CUT AND TRIM PER MECH LAYER 1" at 12393.46,2209.35 h60
  text "N.C. ROUTE" at 12393.46,2057.64 h60
  text "X" at 13072.46,2057.64 h60
  text "V. SCORE" at 13259.46,2057.64 h60
  text "CERTIFICATION:" at 11332.46,1920.64 h60
  text "MATERIALS AND WORKMANSHIP FOR ALL PCBS" at 12057.46,1920.64 h60
  text "TO MEET OR EXCEED THE REQUIREMENTS OF:" at 12057.46,1822.64 h60
  text "X" at 11683.96,1686.13 h60
  text "ANSI IPC-A-600F CLASS ->" at 11822.96,1686.13 h60
  text "X" at 13462.02,1686.13 h60
  text "2" at 13580.96,1686.14 h60
  text "1" at 13265.96,1684.64 h60
  text "3" at 13934.96,1684.64 h60
  text "X" at 11686.02,1526.64 h60
  text "UL 94V-0" at 11822.96,1526.64 h60
  text "X" at 12498.02,1526.64 h60
  text "RoHS" at 12634.96,1526.64 h60
  text "OTHER" at 13279.36,1526.64 h60
  text "PER ORDER" at 13676.42,1526.64 h60
  text "ADDITIONAL REQUIREMENTS:" at 11332.46,1385.64 h60
  text "MICROSECTION:" at 11407.23,1270.64 h60
  text "YES" at 12312.96,1270.64 h60
  text "REQUIRED" at 13174.46,1114.49 h60
  text "BARE BOARD ELEC. TEST:" at 11407.23,1111.64 h60
  text "NONE" at 12712.96,1111.64 h60
  text "X" at 13047.46,1111.64 h60
  text "PER ORDER" at 13766.46,1111.64 h60
  text "MANUFACTURER'S UL:" at 11407.23,954.64 h60
  text "RAIL" at 12572.96,950.35 h60
  text "METAL" at 13064.77,950.35 h60
  text "X" at 13440,950 h60
  text "SILK" at 13576.46,950.35 h60
  text ".Layer_Name" at 577,-858.49 h60
M11 Gerber Information:
  lines w10: -292,-930.17 6308,-930.17 ; -292,-726.83 6310,-726.83 ; -292,-523.5 -292,-1133.5 3713,-1133.5 6310,-1133.5 6310,-523.5 -291.5,-523.5 -291.5,-1133.5 1284,-1133.5 ; 2173,-1133.5 2173,-523.5 ; 3440,-726.83 3440,-523.5 ; 4280,-726.83 4280,-523.5 ; 4902,-1140 4902,-937.17
  text "ALL ARTWORK VIEWED FROM TOP SIDE" at -228.5,-655.67 h60
  text "BOARD #:" at 2248,-655.67 h60
  text ".PRJ_Number" at 2793.5,-655.67 h60
  text "REV:" at 3638,-655.67 h60
  text ".PCB_Rev" at 3929.5,-655.67 h60
  text "SVN REV:" at 4476,-655.67 h60
  text ".VersionControl_RevNumber" at 4982,-655.67 h60
  text "LAYER NAME =" at -228.5,-858.49 h60
  text "PLOT NAME =" at -228.5,-1064.34 h60
  text ".plot_File_Name" at 577,-1064.34 h60
  text "GENERATED    :" at 2250,-1064.34 h60
  text ".Print_Date" at 3119.5,-1064.34 h60
  text ".Print_Time" at 3848.5,-1064.34 h60
  text "TEXAS INSTRUMENTS" at 5113,-1064.34 h60
M12 Stackup:
  drawing of 191 lines, arcs and shapes, not listed
  text "Layer" at 9790.58,7830 h60
  text "Name" at 10200.49,7830 h60
  text "Material" at 11130.23,7830 h60
  text "Thickness" at 11990,7830 h60
  text "Constant" at 12639.84,7830 h60
  text "Board Layer Stack" at 13209.7,7830 h60
  text "1" at 9790.58,7710 h60
  text "Top Overlay" at 10200.49,7710 h60
  text "2" at 9790.58,7590 h60
  text "Top Solder" at 10200.49,7590 h60
  text "Solder Resist" at 11130.23,7590 h60
  text "0.40mil" at 11990,7590 h60
  text "3.5" at 12639.84,7590 h60
  text "3" at 9790.58,7470 h60
  text "Top Layer" at 10200.49,7470 h60
  text "Copper" at 11130.23,7470 h60
  text "1.40mil" at 11990,7470 h60
  text "4" at 9790.58,7350 h60
  text "Dielectric1" at 10200.49,7350 h60
  text "FR-4" at 11130.23,7350 h60
  text "59.20mil" at 11990,7350 h60
  text "4.8" at 12639.84,7350 h60
  text "5" at 9790.58,7230 h60
  text "Bottom Layer" at 10200.49,7230 h60
  text "Copper" at 11130.23,7230 h60
  text "1.40mil" at 11990,7230 h60
  text "6" at 9790.58,7110 h60
  text "Bottom Solder" at 10200.49,7110 h60
  text "Solder Resist" at 11130.23,7110 h60
  text "0.40mil" at 11990,7110 h60
  text "3.5" at 12639.84,7110 h60
  text "7" at 9790.58,6990 h60
  text "Bottom Overlay" at 10200.49,6990 h60
  text ".Layer_Name" at 577,-858.49 h60
M13 Component Bodies Top:
  text ".Layer_Name" at 577,-858.49 h60
M14 Component Bodies Bottom:
  text ".Layer_Name" at 577,-858.49 h60
M15 Courtyards Top:
  text ".Layer_Name" at 577,-858.49 h60
M16 Courtyards Bottom:
  text ".Layer_Name" at 577,-858.49 h60
Drill Drawing:
  circle w1: c5572.73,3221.02 r24.89
  circle w1: c5572.73,2922.35 r14.93
  circle w1: c5572.73,2922.35 r24.89
  lines w1: 5547.84,1877 5572.73,1852.11 5597.62,1877 5572.73,1901.89 5547.84,1877 ; 5547.84,2001.45 5547.84,2013.89 5560.28,2026.34 5547.84,2038.78 5547.84,2051.23 5560.28,2051.23 5572.73,2038.78 5585.17,2051.23 5597.62,2051.23 5597.62,2038.78 5585.17,2026.34 5597.62,2013.89 5597.62,2001.45 5585.17,2001.45 5572.73,2013.89 5560.28,2001.45 5547.84,2001.45 ; 5547.84,2150.78 5597.62,2150.78 5597.62,2200.56 5547.84,2200.56 5547.84,2150.78 ; 5547.84,2312.56 5560.28,2312.56 5560.28,2300.12 5585.17,2300.12 5585.17,2312.56 5597.62,2312.56 5597.62,2337.45 5585.17,2337.45 5585.17,2349.9 5560.28,2349.9 5560.28,2337.45 5547.84,2337.45 5547.84,2312.56 ; 5547.84,2449.45 5572.73,2461.9 5597.62,2449.45 5585.17,2474.34 5597.62,2499.23 5572.73,2486.79 5547.84,2499.23 5560.28,2474.34 5547.84,2449.45 ; 5547.84,2611.23 5560.28,2611.23 5572.73,2598.79 5585.17,2611.23 5597.62,2611.23 5585.17,2623.68 5597.62,2636.12 5585.17,2636.12 5572.73,2648.57 5560.28,2636.12 5547.84,2636.12 5560.28,2623.68 5547.84,2611.23 ; 5547.84,2797.9 5597.62,2797.9 5572.73,2748.12 5547.84,2797.9 ; 5547.84,3046.8 5597.62,3046.8 5597.62,3096.57 5547.84,3096.57 5547.84,3046.8 ; 5557.79,3056.75 5587.66,3056.75 5587.66,3086.62 5557.79,3086.62 5557.79,3056.75
  lines w12: 5480,1807.31 7596.94,1807.31 ; 5480,3300.66 7596.94,3300.66 ; 5850.25,1657.98 5850.25,3450 ; 6207.06,1657.98 6207.06,3450 ; 6868.16,1657.98 6868.16,3450 ; 7152.16,1657.98 7152.16,3450 ; 5480,1657.98 7596.94,1657.98 7596.94,3450 5480,3450 5480,1657.98
  text "Symbol" at 5569.6,3345.47 h72
  text "Quantity" at 5895.05,3345.47 h72
  text "Finished Hole Size" at 6251.86,3345.47 h72
  text "Plated" at 6912.96,3345.47 h72
  text "Hole Type" at 7196.96,3345.47 h72
  text "9" at 5895.05,3196.13 h60
  text "7.87mil (0.200mm)" at 6251.86,3196.13 h60
  text "PTH" at 6912.96,3196.13 h60
  text "Round" at 7196.96,3196.13 h60
  text "169" at 5895.05,3046.8 h60
  text "19.69mil (0.500mm)" at 6251.86,3046.8 h60
  text "PTH" at 6912.96,3046.8 h60
  text "Round" at 7196.96,3046.8 h60
  text "8" at 5895.05,2897.46 h60
  text "33.46mil (0.850mm)" at 6251.86,2897.46 h60
  text "PTH" at 6912.96,2897.46 h60
  text "Round" at 7196.96,2897.46 h60
  text "15" at 5895.05,2748.12 h60
  text "39.37mil (1.000mm)" at 6251.86,2748.12 h60
  text "PTH" at 6912.96,2748.12 h60
  text "Round" at 7196.96,2748.12 h60
  text "37" at 5895.05,2598.79 h60
  text "40.00mil (1.016mm)" at 6251.86,2598.79 h60
  text "PTH" at 6912.96,2598.79 h60
  text "Round" at 7196.96,2598.79 h60
  text "4" at 5895.05,2449.45 h60
  text "51.18mil (1.300mm)" at 6251.86,2449.45 h60
  text "PTH" at 6912.96,2449.45 h60
  text "Round" at 7196.96,2449.45 h60
  text "2" at 5895.05,2300.12 h60
  text "122.05mil (3.100mm)" at 6251.86,2300.12 h60
  text "PTH" at 6912.96,2300.12 h60
  text "Round" at 7196.96,2300.12 h60
  text "4" at 5895.05,2150.78 h60
  text "125.98mil (3.200mm)" at 6251.86,2150.78 h60
  text "PTH" at 6912.96,2150.78 h60
  text "Round" at 7196.96,2150.78 h60
  text "2" at 5895.05,2001.45 h60
  text "29.92mil (0.760mm)" at 6251.86,2001.45 h60
  text "PTH" at 6912.96,2001.45 h60
  text "Slot" at 7196.96,2001.45 h60
  text "1" at 5895.05,1852.11 h60
  text "39.76mil (1.010mm)" at 6251.86,1852.11 h60
  text "PTH" at 6912.96,1852.11 h60
  text "Slot" at 7196.96,1852.11 h60
  text "251 Total" at 5895.05,1702.78 h60
  text ".Layer_Name" at 577,-858.49 h60

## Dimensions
0,0 to 0,3093.63 on M2 Board Dimensions
0,0 to 3536,0 on M2 Board Dimensions
0,-400 to 1000,-400 on M2 Board Dimensions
